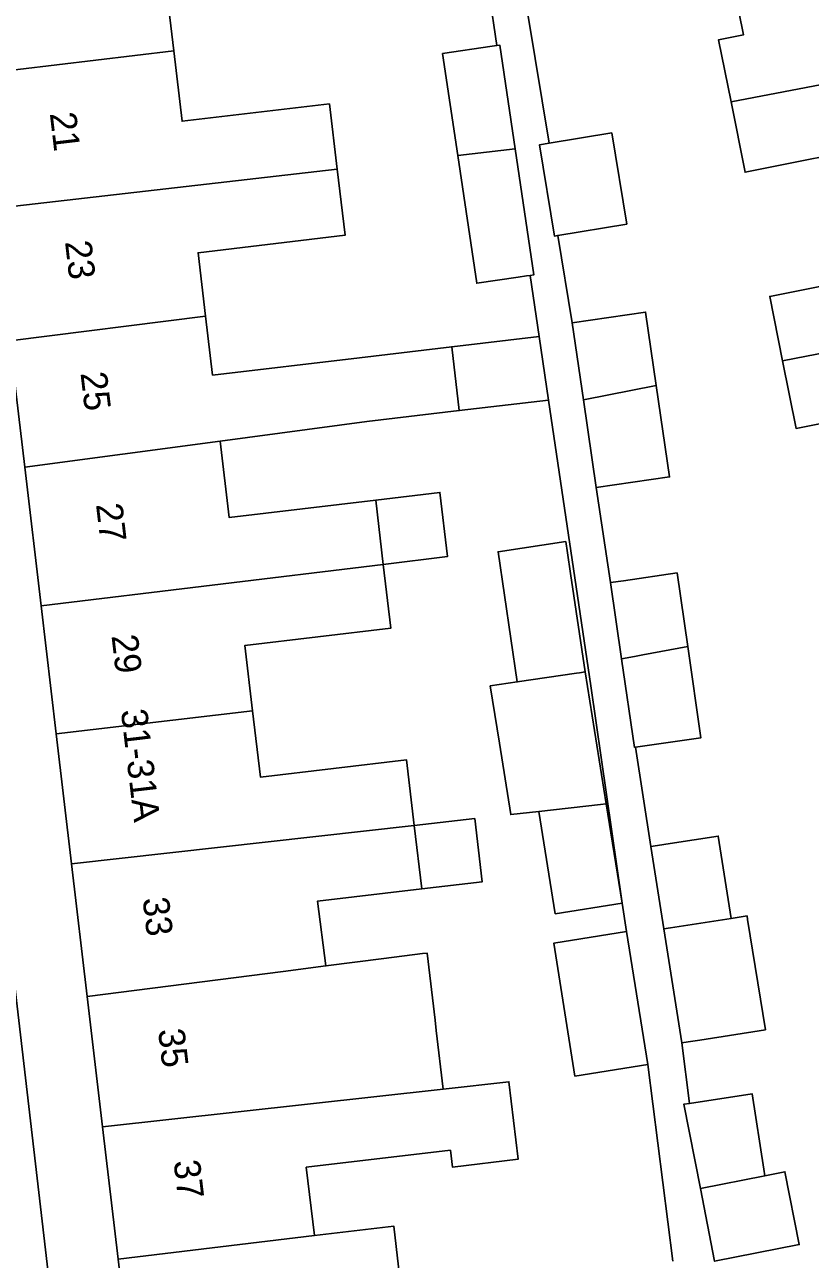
# Model space of a CAD drawing. Extents: x 162250 to 162661, y 380743 to 381606.
# Drawn here: x 162465.47 to 162495.32, y 381013.48 to 381060.4 of the extents above; entities that cross this region are included whole.
import ezdxf

# ---------------------------------------------------------------- set-up
doc = ezdxf.new("R2010")
doc.units = 0
for name, color, linetype in [('IMGEO_Erf', 7, 'Continuous'), ('IMGEO_Pand', 7, 'Continuous'), ('IMGEO_Pand_nummerreeks', 7, 'Continuous'), ('IMGEO_Voetpad_open', 7, 'Continuous')]:
    doc.layers.add(name, color=color, linetype=linetype)

msp = doc.modelspace()

# ---------------------------------------------------------------- linework, layer by layer
at = {"layer": 'IMGEO_Erf'}
for points in [[(162484.331, 381062.348), (162485.396, 381055.893), (162487.773, 381056.285), (162488.345, 381052.821), (162485.725, 381052.389), (162486.272, 381049.07), (162489.06, 381049.475), (162489.465, 381046.685), (162489.969, 381043.214), (162487.181, 381042.81), (162487.73, 381039.196), (162488.216, 381039.266), (162490.255, 381039.562), (162490.661, 381036.767), (162491.164, 381033.302), (162489.648, 381033.082), (162489.125, 381033.006), (162488.68, 381032.942), (162489.264, 381029.162), (162489.512, 381029.201), (162489.999, 381029.277), (162491.822, 381029.562), (162492.311, 381026.432), (162492.914, 381026.527), (162492.935, 381026.389), (162493.61, 381022.201), (162491.124, 381021.812), (162490.68, 381021.742), (162490.432, 381021.703), (162490.732, 381019.403), (162493.111, 381019.764), (162493.546, 381016.907), (162493.585, 381016.652), (162494.356, 381016.804), (162494.9, 381014.038), (162491.683, 381013.405)], [(162498.174, 381055.854), (162492.84, 381054.791), (162492.307, 381057.464), (162491.836, 381059.825), (162492.778, 381060.013), (162492.266, 381062.582)], [(162470.858, 381061.733), (162471.133, 381059.41), (162471.45, 381056.729), (162477.049, 381057.391), (162477.343, 381054.906), (162477.64, 381052.395), (162472.059, 381051.735), (162472.344, 381049.317), (162472.608, 381047.085), (162478.188, 381047.744), (162481.696, 381048.158), (162485.014, 381048.549), (162484.677, 381050.873), (162484.531, 381050.851), (162484.225, 381050.806), (162482.642, 381050.571), (162481.921, 381055.429), (162481.346, 381059.303), (162483.236, 381059.583), (162483.41, 381059.609), (162483.122, 381061.593)], [(162500, 381046.093), (162494.776, 381045.056), (162494.265, 381047.618), (162493.776, 381050.073), (162499.115, 381051.137)], [(162462.62, 381045.107), (162467.864, 381000), (162469.785, 380983.331), (162472.547, 380983.649), (162471.948, 380988.726), (162471.367, 380993.647), (162470.788, 380998.552), (162470.617, 381000), (162470.191, 381003.608), (162469.621, 381008.437), (162469.025, 381013.484), (162468.432, 381018.509), (162467.848, 381023.463), (162467.253, 381028.502), (162466.67, 381033.444), (162466.095, 381038.309), (162465.473, 381043.58), (162464.907, 381048.38)], [(162490.1, 381013.408), (162489.141, 381020.884), (162486.374, 381020.443), (162485.569, 381025.491), (162488.337, 381025.932), (162488.164, 381027.017), (162486.984, 381035.273), (162485.373, 381046.133), (162481.983, 381045.732), (162478.475, 381045.317), (162472.893, 381044.568), (162473.235, 381041.676), (162478.806, 381042.335), (162481.245, 381042.624), (162481.533, 381040.185), (162479.095, 381039.889), (162479.382, 381037.465), (162473.836, 381036.809), (162474.131, 381034.32), (162474.428, 381031.807), (162479.974, 381032.463), (162480.269, 381029.968), (162482.572, 381030.227), (162482.856, 381027.829), (162480.554, 381027.557), (162476.598, 381027.089), (162476.914, 381024.625), (162479.116, 381024.908), (162480.582, 381025.096), (162480.758, 381025.118), (162481.06, 381022.567), (162481.106, 381022.176), (162481.37, 381019.95), (162483.867, 381020.228), (162484.215, 381017.278), (162481.721, 381016.983), (162481.645, 381017.624), (162476.169, 381016.977), (162476.476, 381014.38), (162479.49, 381014.742), (162479.765, 381012.423)]]:
    msp.add_lwpolyline(points, dxfattribs=at)
msp.add_lwpolyline([(162488.164, 381027.017), (162485.63, 381026.613), (162485.01, 381030.502), (162483.939, 381030.381), (162483.506, 381033.092), (162483.158, 381035.269), (162484.187, 381035.421), (162483.454, 381040.37), (162486.029, 381040.752), (162486.091, 381040.332), (162486.209, 381039.539), (162486.763, 381035.803), (162487.562, 381030.789)], close=True, dxfattribs=at)
at = {"layer": 'IMGEO_Pand'}
for points in [[(162504.062, 381064.51), (162504.398, 381064.577), (162504.321, 381064.962), (162500, 381064.109), (162496.987, 381063.514), (162496.648, 381063.447), (162492.266, 381062.582), (162492.778, 381060.013), (162491.836, 381059.825), (162492.307, 381057.464), (162500, 381058.938), (162504.982, 381059.893)], [(162471.133, 381059.41), (162470.858, 381061.733), (162476.415, 381062.39), (162476.118, 381064.904), (162463.144, 381063.31), (162463.71, 381058.519)], [(162492.307, 381057.464), (162492.84, 381054.791), (162498.174, 381055.854), (162498.627, 381053.581), (162500, 381053.854), (162505.95, 381055.037), (162504.982, 381059.893), (162500, 381058.938)], [(162471.133, 381059.41), (162463.71, 381058.519), (162464.312, 381053.418), (162477.343, 381054.906), (162477.049, 381057.391), (162471.45, 381056.729)], [(162483.41, 381059.609), (162483.236, 381059.583), (162481.346, 381059.303), (162481.921, 381055.429), (162484.107, 381055.678), (162483.522, 381059.626)], [(162487.773, 381056.285), (162485.396, 381055.893), (162485.027, 381055.832), (162485.599, 381052.368), (162485.725, 381052.389), (162488.345, 381052.821)], [(162484.107, 381055.678), (162481.921, 381055.429), (162482.642, 381050.571), (162484.225, 381050.806), (162484.531, 381050.851), (162484.677, 381050.873), (162484.817, 381050.894)], [(162472.344, 381049.317), (162472.059, 381051.735), (162477.64, 381052.395), (162477.343, 381054.906), (162464.312, 381053.418), (162464.907, 381048.38)], [(162494.265, 381047.618), (162500, 381048.733), (162506.938, 381050.081), (162505.95, 381055.037), (162500, 381053.854), (162498.627, 381053.581), (162499.115, 381051.137), (162493.776, 381050.073)], [(162494.265, 381047.618), (162494.776, 381045.056), (162500, 381046.093), (162500.501, 381043.798), (162507.897, 381045.266), (162506.938, 381050.081), (162500, 381048.733)], [(162486.697, 381046.147), (162489.465, 381046.685), (162489.06, 381049.475), (162486.272, 381049.07)], [(162465.473, 381043.58), (162472.893, 381044.568), (162478.475, 381045.317), (162481.983, 381045.732), (162481.696, 381048.158), (162478.188, 381047.744), (162472.608, 381047.085), (162472.344, 381049.317), (162464.907, 381048.38)], [(162485.014, 381048.549), (162481.696, 381048.158), (162481.983, 381045.732), (162485.373, 381046.133)], [(162486.697, 381046.147), (162487.181, 381042.81), (162489.969, 381043.214), (162489.465, 381046.685)], [(162466.095, 381038.309), (162479.095, 381039.889), (162478.806, 381042.335), (162473.235, 381041.676), (162472.893, 381044.568), (162465.473, 381043.58)], [(162478.806, 381042.335), (162479.095, 381039.889), (162481.533, 381040.185), (162481.245, 381042.624)], [(162484.187, 381035.421), (162486.44, 381035.755), (162486.548, 381035.771), (162486.763, 381035.803), (162486.209, 381039.539), (162486.091, 381040.332), (162486.029, 381040.752), (162483.454, 381040.37)], [(162466.095, 381038.309), (162466.67, 381033.444), (162474.131, 381034.32), (162473.836, 381036.809), (162479.382, 381037.465), (162479.095, 381039.889)], [(162487.73, 381039.196), (162487.724, 381039.195), (162488.145, 381036.293), (162488.634, 381036.385), (162488.954, 381036.445), (162490.661, 381036.767), (162490.255, 381039.562), (162488.216, 381039.266)], [(162490.661, 381036.767), (162488.954, 381036.445), (162488.634, 381036.385), (162488.145, 381036.293), (162488.633, 381032.935), (162488.68, 381032.942), (162489.125, 381033.006), (162489.648, 381033.082), (162491.164, 381033.302)], [(162486.763, 381035.803), (162486.548, 381035.771), (162486.44, 381035.755), (162484.187, 381035.421), (162483.158, 381035.269), (162483.506, 381033.092), (162483.939, 381030.381), (162485.01, 381030.502), (162487.346, 381030.765), (162487.562, 381030.789)], [(162480.269, 381029.968), (162479.974, 381032.463), (162474.428, 381031.807), (162474.131, 381034.32), (162466.67, 381033.444), (162467.253, 381028.502)], [(162487.346, 381030.765), (162485.01, 381030.502), (162485.63, 381026.613), (162488.164, 381027.017), (162487.562, 381030.789)], [(162480.269, 381029.968), (162480.554, 381027.557), (162482.856, 381027.829), (162482.572, 381030.227)], [(162480.269, 381029.968), (162467.253, 381028.502), (162467.848, 381023.463), (162475.296, 381024.418), (162476.914, 381024.625), (162476.598, 381027.089), (162480.554, 381027.557)], [(162489.264, 381029.162), (162489.754, 381026.033), (162490.002, 381026.072), (162492.311, 381026.432), (162491.822, 381029.562), (162489.999, 381029.277), (162489.512, 381029.201)], [(162492.311, 381026.432), (162490.002, 381026.072), (162489.754, 381026.033), (162490.432, 381021.703), (162490.68, 381021.742), (162491.124, 381021.812), (162493.61, 381022.201), (162492.935, 381026.389), (162492.914, 381026.527)], [(162488.337, 381025.932), (162485.569, 381025.491), (162486.374, 381020.443), (162489.141, 381020.884)], [(162476.914, 381024.625), (162475.296, 381024.418), (162467.848, 381023.463), (162468.432, 381018.509), (162481.37, 381019.95), (162481.106, 381022.176), (162481.06, 381022.567), (162480.758, 381025.118), (162480.582, 381025.096), (162479.116, 381024.908)], [(162481.37, 381019.95), (162468.432, 381018.509), (162469.025, 381013.484), (162476.476, 381014.38), (162476.169, 381016.977), (162481.645, 381017.624), (162481.721, 381016.983), (162484.215, 381017.278), (162483.867, 381020.228)], [(162490.732, 381019.403), (162490.511, 381019.369), (162491.14, 381016.168), (162493.585, 381016.652), (162493.546, 381016.907), (162493.111, 381019.764)], [(162493.585, 381016.652), (162491.14, 381016.168), (162491.683, 381013.405), (162494.9, 381014.038), (162494.356, 381016.804)], [(162476.476, 381014.38), (162469.025, 381013.484), (162469.621, 381008.437), (162482.592, 381010.047), (162482.276, 381012.72), (162479.765, 381012.423), (162479.49, 381014.742)]]:
    msp.add_lwpolyline(points, close=True, dxfattribs=at)
at = {"layer": 'IMGEO_Voetpad_open'}
for points in [[(162462.351, 381035.014), (162465.026, 381012.162), (162465.322, 381009.581), (162467.991, 380986.747), (162468.323, 380984.109), (162470.398, 380966.255), (162470.699, 380963.849), (162471.572, 380963.846), (162471.135, 380971.612), (162469.897, 380982.357), (162469.785, 380983.331), (162467.864, 381000), (162462.62, 381045.107), (162455.21, 381107.834)], [(162491.683, 381013.405), (162491.14, 381016.168), (162490.511, 381019.369), (162490.732, 381019.403), (162490.432, 381021.703), (162489.754, 381026.033), (162489.264, 381029.162), (162488.68, 381032.942), (162488.633, 381032.935), (162488.145, 381036.293), (162487.724, 381039.195), (162487.73, 381039.196), (162487.181, 381042.81), (162486.697, 381046.147), (162486.272, 381049.07), (162485.725, 381052.389), (162485.599, 381052.368), (162485.027, 381055.832), (162485.396, 381055.893), (162484.331, 381062.348)], [(162483.122, 381061.593), (162483.41, 381059.609), (162483.522, 381059.626), (162484.107, 381055.678), (162484.817, 381050.894), (162484.677, 381050.873), (162485.014, 381048.549), (162485.373, 381046.133), (162486.984, 381035.273), (162488.164, 381027.017), (162488.337, 381025.932), (162489.141, 381020.884), (162490.1, 381013.408)]]:
    msp.add_lwpolyline(points, dxfattribs=at)

# ---------------------------------------------------------------- texts
at = {"layer": 'IMGEO_Pand_nummerreeks'}
for s, rotation, p in [('21', 276.7316, (162466.423, 381057.027)), ('23', 276.7316, (162467, 381052.148)), ('25', 276.7316, (162467.589, 381047.156)), ('27', 276.7316, (162468.178, 381042.165)), ('29', 276.7316, (162468.767, 381037.173)), ('31-31A', 276.7591, (162469.122, 381034.341)), ('33', 276.732, (162469.946, 381027.189)), ('35', 276.732, (162470.535, 381022.197)), ('37', 276.732, (162471.124, 381017.205))]:
    msp.add_text(s, height=1, rotation=rotation, dxfattribs=at).set_placement(p)

doc.saveas('drawing.dxf')
